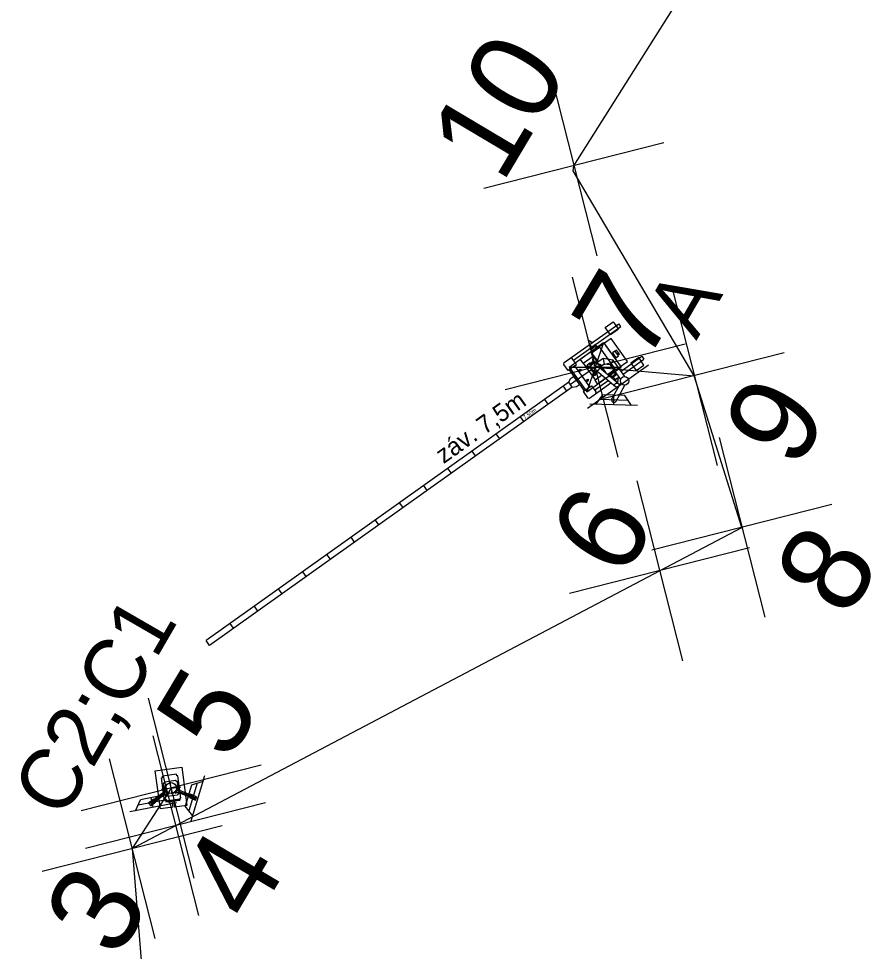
# Model space of a CAD drawing. Extents: x -553584 to -553445, y -1067272 to -1066959.
# Drawn here: x -553576.22 to -553561.85, y -1067237.72 to -1067222.01 of the extents above; entities that cross this region are included whole.
import ezdxf

# ---------------------------------------------------------------- set-up
doc = ezdxf.new("R2010")
doc.units = 0
for name, color, linetype in [('Body', 7, 'Continuous'), ('Default', 7, 'Continuous'), ('Křížky', 7, 'Continuous'), ('Nová kabelizace', 7, 'Continuous'), ('nové prvky ZZ', 7, 'Continuous')]:
    doc.layers.add(name, color=color, linetype=linetype)

# ---------------------------------------------------------------- blocks, each defined once
blk = doc.blocks.new('Křížek')
at = {"layer": 'Křížky'}
for p, q in [((8.84, -8.84), (-8.84, 8.84)), ((8.84, -8.84), (-8.84, 8.84)), ((8.84, -8.84), (-8.84, 8.84)), ((8.84, 8.84), (-8.84, -8.84))]:
    blk.add_line(p, q, dxfattribs=at)

msp = doc.modelspace()

# ---------------------------------------------------------------- linework, layer by layer
at = {"layer": 'Nová kabelizace'}
for p, q in [((-553566.514, -1067227.883), (-553564.846, -1067228.027)), ((-553574.308, -1067235.992), (-553564.043, -1067230.581)), ((-553574.308, -1067235.992), (-553574.04, -1067239.262))]:
    msp.add_line(p, q, dxfattribs=at)
msp.add_lwpolyline([(-553564.043, -1067230.581), (-553564.846, -1067228.027), (-553566.884, -1067224.575), (-553566.87, -1067224.492), (-553564.137, -1067220.156)], dxfattribs=at)
at = {"layer": 'nové prvky ZZ'}
for p, q in [((-553567.034, -1067227.806), (-553566.116, -1067227.152)), ((-553566.081, -1067227.2), (-553566.116, -1067227.152)), ((-553566.879, -1067227.768), (-553566.081, -1067227.2)), ((-553566.951, -1067227.882), (-553566.373, -1067227.47)), ((-553566.373, -1067227.47), (-553566.655, -1067228.297)), ((-553566.605, -1067227.44), (-553566.626, -1067227.455)), ((-553566.626, -1067227.455), (-553566.622, -1067227.461)), ((-553566.622, -1067227.461), (-553566.626, -1067227.463)), ((-553566.626, -1067227.463), (-553566.618, -1067227.473)), ((-553566.605, -1067227.44), (-553566.601, -1067227.446)), ((-553566.601, -1067227.446), (-553566.598, -1067227.443)), ((-553566.598, -1067227.443), (-553566.59, -1067227.453)), ((-553566.374, -1067227.469), (-553566.077, -1067227.884)), ((-553566.569, -1067227.616), (-553566.763, -1067227.754)), ((-553566.595, -1067227.507), (-553566.593, -1067227.492)), ((-553566.592, -1067227.516), (-553566.595, -1067227.507)), ((-553566.569, -1067227.547), (-553566.592, -1067227.516)), ((-553566.569, -1067227.631), (-553566.579, -1067227.646)), ((-553566.579, -1067227.646), (-553566.574, -1067227.663)), ((-553566.445, -1067227.543), (-553566.569, -1067227.631)), ((-553566.511, -1067227.538), (-553566.564, -1067227.576)), ((-553566.438, -1067227.554), (-553566.564, -1067227.644)), ((-553566.564, -1067227.644), (-553566.564, -1067227.658)), ((-553566.339, -1067227.518), (-553566.077, -1067227.884)), ((-553566.179, -1067227.617), (-553566.181, -1067227.614)), ((-553566.899, -1067227.739), (-553566.931, -1067227.733)), ((-553566.826, -1067227.841), (-553566.899, -1067227.739)), ((-553566.763, -1067227.754), (-553566.72, -1067227.814)), ((-553566.713, -1067227.816), (-553566.549, -1067227.699)), ((-553566.545, -1067227.786), (-553566.598, -1067227.824)), ((-553566.534, -1067227.793), (-553566.591, -1067227.833)), ((-553566.574, -1067227.663), (-553566.475, -1067227.803)), ((-553566.564, -1067227.658), (-553566.465, -1067227.796)), ((-553566.558, -1067227.749), (-553566.56, -1067227.759)), ((-553566.56, -1067227.759), (-553566.558, -1067227.768)), ((-553566.553, -1067227.74), (-553566.558, -1067227.749)), ((-553566.558, -1067227.768), (-553566.538, -1067227.796)), ((-553566.531, -1067227.724), (-553566.553, -1067227.74)), ((-553566.524, -1067227.734), (-553566.551, -1067227.753)), ((-553566.551, -1067227.753), (-553566.549, -1067227.762)), ((-553566.549, -1067227.762), (-553566.533, -1067227.784)), ((-553566.38, -1067227.736), (-553566.484, -1067227.81)), ((-553566.209, -1067227.766), (-553566.38, -1067227.736)), ((-553566.38, -1067227.736), (-553566.361, -1067227.83)), ((-553566.209, -1067227.766), (-553566.26, -1067227.846)), ((-553566.012, -1067228.043), (-553566.209, -1067227.766)), ((-553566.077, -1067227.951), (-553565.725, -1067227.7)), ((-553566.043, -1067227.999), (-553565.691, -1067227.748)), ((-553565.725, -1067227.7), (-553565.691, -1067227.748)), ((-553567.039, -1067227.838), (-553567.034, -1067227.806)), ((-553566.966, -1067227.94), (-553567.039, -1067227.838)), ((-553566.952, -1067227.93), (-553566.966, -1067227.94)), ((-553566.951, -1067227.882), (-553566.655, -1067228.297)), ((-553566.951, -1067227.882), (-553566.077, -1067227.884)), ((-553566.514, -1067227.883), (-553566.927, -1067228.178)), ((-553566.855, -1067227.861), (-553566.826, -1067227.841)), ((-553566.72, -1067227.814), (-553566.716, -1067227.811)), ((-553566.716, -1067227.811), (-553566.713, -1067227.816)), ((-553566.713, -1067227.816), (-553566.514, -1067228.095)), ((-553566.655, -1067228.297), (-553566.077, -1067227.884)), ((-553565.615, -1067227.847), (-553566.641, -1067228.578)), ((-553566.569, -1067227.941), (-553566.537, -1067227.969)), ((-553566.541, -1067227.95), (-553566.53, -1067227.96)), ((-553566.501, -1067227.974), (-553566.519, -1067227.96)), ((-553566.518, -1067227.886), (-553566.51, -1067227.88)), ((-553566.511, -1067227.887), (-553566.517, -1067227.879)), ((-553566.483, -1067227.953), (-553566.498, -1067227.964)), ((-553566.474, -1067227.961), (-553566.491, -1067227.973)), ((-553566.169, -1067228.212), (-553566.487, -1067227.95)), ((-553566.469, -1067227.817), (-553566.434, -1067227.845)), ((-553566.453, -1067227.845), (-553566.442, -1067227.854)), ((-553566.425, -1067227.876), (-553566.442, -1067227.887)), ((-553566.127, -1067228.157), (-553566.442, -1067227.896)), ((-553566.424, -1067227.877), (-553566.439, -1067227.865)), ((-553566.424, -1067227.846), (-553566.407, -1067227.859)), ((-553566.407, -1067227.859), (-553566.424, -1067227.877)), ((-553566.423, -1067227.876), (-553566.359, -1067227.964)), ((-553566.361, -1067227.83), (-553566.419, -1067227.871)), ((-553566.414, -1067227.868), (-553566.326, -1067227.992)), ((-553566.26, -1067227.846), (-553566.361, -1067227.83)), ((-553566.196, -1067227.935), (-553566.303, -1067228.011)), ((-553566.26, -1067227.846), (-553566.084, -1067228.092)), ((-553566.779, -1067228.172), (-553566.875, -1067228.037)), ((-553566.534, -1067227.979), (-553566.516, -1067227.993)), ((-553566.522, -1067228.268), (-553566.296, -1067228.107)), ((-553566.516, -1067227.993), (-553566.501, -1067227.974)), ((-553566.515, -1067228.102), (-553566.511, -1067228.1)), ((-553566.472, -1067228.163), (-553566.515, -1067228.102)), ((-553566.514, -1067228.095), (-553566.405, -1067228.018)), ((-553566.511, -1067228.1), (-553566.514, -1067228.095)), ((-553566.472, -1067228.163), (-553566.342, -1067228.07)), ((-553566.22, -1067227.966), (-553566.294, -1067228.019)), ((-553566.293, -1067228.018), (-553566.281, -1067228.02)), ((-553566.237, -1067228.066), (-553566.148, -1067228.002)), ((-553566.213, -1067228.048), (-553566.19, -1067228.08)), ((-553566.19, -1067228.105), (-553566.114, -1067228.05)), ((-553566.19, -1067228.08), (-553566.182, -1067228.085)), ((-553566.182, -1067228.085), (-553566.168, -1067228.089)), ((-553566.151, -1067228.129), (-553566.159, -1067228.119)), ((-553566.123, -1067228.117), (-553566.144, -1067228.132)), ((-553566.123, -1067228.109), (-553566.131, -1067228.099)), ((-553566.127, -1067228.111), (-553566.123, -1067228.109)), ((-553566.123, -1067228.117), (-553566.127, -1067228.111)), ((-553566.956, -1067228.137), (-553573.064, -1067232.489)), ((-553566.898, -1067228.218), (-553573.006, -1067232.57)), ((-553567.052, -1067228.206), (-553566.995, -1067228.287)), ((-553566.898, -1067228.218), (-553566.956, -1067228.137)), ((-553566.609, -1067228.403), (-553566.249, -1067228.146)), ((-553566.603, -1067228.215), (-553566.574, -1067228.195)), ((-553566.574, -1067228.195), (-553566.501, -1067228.297)), ((-553566.232, -1067228.417), (-553566.082, -1067228.146)), ((-553566.162, -1067228.455), (-553566.011, -1067228.186)), ((-553566.148, -1067228.126), (-553566.151, -1067228.129)), ((-553566.144, -1067228.132), (-553566.148, -1067228.126)), ((-553567.305, -1067228.508), (-553567.363, -1067228.427)), ((-553566.699, -1067228.284), (-553566.713, -1067228.294)), ((-553566.713, -1067228.294), (-553566.64, -1067228.397)), ((-553566.64, -1067228.397), (-553566.609, -1067228.403)), ((-553566.501, -1067228.297), (-553566.506, -1067228.329)), ((-553566.501, -1067228.51), (-553566.381, -1067228.35)), ((-553565.956, -1067228.444), (-553566.441, -1067228.43)), ((-553566.011, -1067228.361), (-553566.381, -1067228.35)), ((-553566.193, -1067228.431), (-553566.205, -1067228.443)), ((-553566.205, -1067228.431), (-553566.193, -1067228.443)), ((-553566.201, -1067228.519), (-553566.196, -1067228.355)), ((-553565.901, -1067228.528), (-553566.011, -1067228.361)), ((-553565.801, -1067228.531), (-553566.601, -1067228.507)), ((-553567.712, -1067228.798), (-553567.77, -1067228.717)), ((-553568.12, -1067229.088), (-553568.177, -1067229.008)), ((-553568.527, -1067229.379), (-553568.584, -1067229.298)), ((-553568.934, -1067229.669), (-553568.992, -1067229.588)), ((-553569.341, -1067229.959), (-553569.399, -1067229.878)), ((-553569.748, -1067230.249), (-553569.806, -1067230.168)), ((-553570.156, -1067230.539), (-553570.213, -1067230.458)), ((-553570.563, -1067230.829), (-553570.62, -1067230.748)), ((-553570.97, -1067231.119), (-553571.028, -1067231.039)), ((-553571.377, -1067231.41), (-553571.435, -1067231.329)), ((-553571.784, -1067231.7), (-553571.842, -1067231.619)), ((-553572.192, -1067231.99), (-553572.249, -1067231.909)), ((-553572.599, -1067232.28), (-553572.656, -1067232.199)), ((-553573.006, -1067232.57), (-553573.064, -1067232.489)), ((-553573.919, -1067234.68), (-553573.473, -1067234.62)), ((-553573.833, -1067235.324), (-553573.919, -1067234.68)), ((-553573.473, -1067234.62), (-553573.387, -1067235.264)), ((-553573.816, -1067234.802), (-553573.796, -1067234.8)), ((-553573.765, -1067235.179), (-553573.816, -1067234.802)), ((-553573.562, -1067234.74), (-553573.799, -1067234.771)), ((-553573.796, -1067234.8), (-553573.799, -1067234.771)), ((-553573.78, -1067234.903), (-553573.755, -1067234.87)), ((-553573.576, -1067234.846), (-553573.755, -1067234.87)), ((-553573.653, -1067234.972), (-553573.666, -1067234.872)), ((-553573.542, -1067234.872), (-553573.576, -1067234.846)), ((-553573.558, -1067234.768), (-553573.562, -1067234.74)), ((-553573.538, -1067234.765), (-553573.558, -1067234.768)), ((-553573.518, -1067235.049), (-553573.542, -1067234.872)), ((-553573.487, -1067235.142), (-553573.538, -1067234.765)), ((-553573.091, -1067234.764), (-553573.318, -1067235.532)), ((-553573.12, -1067234.86), (-553573.309, -1067234.924)), ((-553573.653, -1067234.972), (-553574.308, -1067235.992)), ((-553573.653, -1067234.972), (-553573.816, -1067234.994)), ((-553573.756, -1067235.084), (-553573.78, -1067234.903)), ((-553573.771, -1067234.999), (-553573.744, -1067234.978)), ((-553573.706, -1067235.083), (-553573.771, -1067234.999)), ((-553573.768, -1067234.937), (-553573.735, -1067234.932)), ((-553573.754, -1067235.042), (-553573.768, -1067234.937)), ((-553573.653, -1067234.972), (-553573.489, -1067234.95)), ((-553573.653, -1067234.972), (-553573.639, -1067235.073)), ((-553573.53, -1067234.963), (-553573.571, -1067235.061)), ((-553573.565, -1067234.948), (-553573.53, -1067234.963)), ((-553573.516, -1067235.029), (-553573.283, -1067235.125)), ((-553573.508, -1067235.01), (-553573.326, -1067235.085)), ((-553573.309, -1067234.924), (-553573.414, -1067235.279)), ((-553573.214, -1067234.892), (-553573.352, -1067235.357)), ((-553574.249, -1067235.353), (-553574.167, -1067235.171)), ((-553573.732, -1067235.17), (-553574.208, -1067235.262)), ((-553573.804, -1067235.1), (-553574.167, -1067235.171)), ((-553573.944, -1067235.159), (-553573.995, -1067235.273)), ((-553573.954, -1067235.296), (-553573.985, -1067235.136)), ((-553573.77, -1067235.062), (-553573.97, -1067235.216)), ((-553573.782, -1067235.047), (-553573.938, -1067235.167)), ((-553573.757, -1067235.079), (-553573.914, -1067235.199)), ((-553573.66, -1067235.239), (-553573.804, -1067235.1)), ((-553573.765, -1067235.179), (-553573.745, -1067235.176)), ((-553573.756, -1067235.084), (-553573.725, -1067235.109)), ((-553573.717, -1067235.037), (-553573.754, -1067235.042)), ((-553573.745, -1067235.176), (-553573.741, -1067235.205)), ((-553573.743, -1067235.19), (-553573.506, -1067235.159)), ((-553573.741, -1067235.205), (-553573.504, -1067235.173)), ((-553573.725, -1067235.109), (-553573.544, -1067235.085)), ((-553573.676, -1067235.06), (-553573.706, -1067235.083)), ((-553573.571, -1067235.061), (-553573.602, -1067235.048)), ((-553573.518, -1067235.049), (-553573.544, -1067235.085)), ((-553573.524, -1067235.046), (-553573.341, -1067235.122)), ((-553573.487, -1067235.142), (-553573.507, -1067235.144)), ((-553573.507, -1067235.144), (-553573.504, -1067235.173)), ((-553573.205, -1067235.148), (-553573.362, -1067235.102)), ((-553573.345, -1067235.131), (-553573.222, -1067235.119)), ((-553573.244, -1067235.173), (-553573.319, -1067235.082)), ((-553573.561, -1067235.22), (-553574.347, -1067235.372)), ((-553574.031, -1067235.226), (-553573.914, -1067235.207)), ((-553573.625, -1067235.296), (-553573.833, -1067235.324)), ((-553573.608, -1067235.19), (-553573.638, -1067235.194)), ((-553573.638, -1067235.194), (-553573.625, -1067235.296)), ((-553573.608, -1067235.19), (-553573.595, -1067235.292)), ((-553573.387, -1067235.264), (-553573.595, -1067235.292)), ((-553573.29, -1067235.436), (-553573.414, -1067235.279))]:
    msp.add_line(p, q, dxfattribs=at)
for points in [[(-553566.119, -1067227.246), (-553566.253, -1067227.341), (-553566.342, -1067227.215), (-553566.209, -1067227.12)], [(-553566.246, -1067227.4), (-553566.445, -1067227.543), (-553566.169, -1067227.93), (-553565.97, -1067227.788)], [(-553566.509, -1067227.504), (-553566.597, -1067227.567), (-553566.589, -1067227.579), (-553566.501, -1067227.516)], [(-553566.464, -1067227.534), (-553566.505, -1067227.564), (-553566.495, -1067227.578), (-553566.453, -1067227.548)], [(-553566.529, -1067227.785), (-553566.522, -1067227.78), (-553566.511, -1067227.795), (-553566.518, -1067227.8)], [(-553565.78, -1067227.721), (-553565.914, -1067227.816), (-553565.824, -1067227.942), (-553565.691, -1067227.847)], [(-553566.855, -1067227.861), (-553566.952, -1067227.93), (-553566.699, -1067228.284), (-553566.603, -1067228.215)], [(-553566.644, -1067227.857), (-553566.657, -1067227.867), (-553566.644, -1067227.886), (-553566.631, -1067227.876)], [(-553566.544, -1067227.997), (-553566.557, -1067228.007), (-553566.544, -1067228.026), (-553566.531, -1067228.016)], [(-553573.722, -1067235.061), (-553573.757, -1067235.016), (-553573.787, -1067235.04), (-553573.753, -1067235.085)], [(-553573.541, -1067234.988), (-553573.562, -1067235.04), (-553573.527, -1067235.055), (-553573.505, -1067235.003)], [(-553573.908, -1067235.206), (-553573.944, -1067235.159), (-553574.031, -1067235.226), (-553573.995, -1067235.273)], [(-553573.323, -1067235.077), (-553573.345, -1067235.131), (-553573.244, -1067235.173), (-553573.222, -1067235.119)]]:
    msp.add_lwpolyline(points, close=True, dxfattribs=at)
for points in [[(-553566.618, -1067227.473), (-553566.622, -1067227.476), (-553566.611, -1067227.492)], [(-553566.611, -1067227.492), (-553566.62, -1067227.499), (-553566.614, -1067227.507), (-553566.56, -1067227.468), (-553566.566, -1067227.46), (-553566.575, -1067227.467)], [(-553566.575, -1067227.467), (-553566.587, -1067227.451), (-553566.59, -1067227.453)], [(-553566.564, -1067227.576), (-553566.586, -1067227.592), (-553566.566, -1067227.62), (-553566.5, -1067227.573)], [(-553566.511, -1067227.538), (-553566.518, -1067227.528), (-553566.571, -1067227.566), (-553566.564, -1067227.576)], [(-553566.475, -1067227.542), (-553566.489, -1067227.523), (-553566.511, -1067227.538)], [(-553566.181, -1067227.614), (-553566.222, -1067227.644), (-553566.164, -1067227.725), (-553566.118, -1067227.692), (-553566.143, -1067227.657)], [(-553566.122, -1067227.642), (-553566.153, -1067227.598), (-553566.179, -1067227.617), (-553566.148, -1067227.661), (-553566.132, -1067227.649)], [(-553566.132, -1067227.649), (-553566.115, -1067227.673), (-553566.105, -1067227.666), (-553566.122, -1067227.642)], [(-553566.519, -1067227.804), (-553566.516, -1067227.802), (-553566.532, -1067227.78), (-553566.539, -1067227.786), (-553566.526, -1067227.805)], [(-553566.754, -1067227.937), (-553566.751, -1067227.941), (-553566.782, -1067227.964), (-553566.799, -1067227.94), (-553566.768, -1067227.918), (-553566.765, -1067227.922)], [(-553566.765, -1067227.922), (-553566.758, -1067227.917), (-553566.747, -1067227.932), (-553566.754, -1067227.937)], [(-553566.588, -1067227.854), (-553566.61, -1067227.822), (-553566.649, -1067227.85), (-553566.626, -1067227.883), (-553566.589, -1067227.857)], [(-553566.583, -1067227.844), (-553566.608, -1067227.81), (-553566.615, -1067227.815), (-553566.588, -1067227.854), (-553566.588, -1067227.854)], [(-553566.526, -1067227.955), (-553566.547, -1067227.98), (-553566.54, -1067227.986), (-553566.515, -1067227.956)], [(-553566.515, -1067227.956), (-553566.504, -1067227.972)], [(-553566.502, -1067227.975), (-553566.482, -1067228.004), (-553566.474, -1067227.998), (-553566.504, -1067227.955)], [(-553566.446, -1067227.859), (-553566.425, -1067227.833), (-553566.418, -1067227.839), (-553566.443, -1067227.869)], [(-553566.18, -1067227.958), (-553566.21, -1067227.98), (-553566.22, -1067227.966), (-553566.19, -1067227.944)], [(-553566.956, -1067228.137), (-553566.926, -1067228.075), (-553566.875, -1067228.038)], [(-553566.632, -1067228.108), (-553566.629, -1067228.113), (-553566.66, -1067228.135), (-553566.677, -1067228.111), (-553566.646, -1067228.089), (-553566.643, -1067228.093)], [(-553566.643, -1067228.093), (-553566.636, -1067228.088), (-553566.625, -1067228.104), (-553566.632, -1067228.108)], [(-553566.541, -1067227.984), (-553566.549, -1067227.99), (-553566.526, -1067228.023), (-553566.487, -1067227.996)], [(-553566.265, -1067228.043), (-553566.281, -1067228.02), (-553566.215, -1067227.973)], [(-553566.24, -1067228.031), (-553566.261, -1067228.046)], [(-553566.246, -1067228.058), (-553566.159, -1067227.996), (-553566.152, -1067228.005), (-553566.237, -1067228.066)], [(-553566.187, -1067227.993), (-553566.176, -1067228.008), (-553566.229, -1067228.046), (-553566.24, -1067228.031)], [(-553566.186, -1067228.108), (-553566.189, -1067228.104), (-553566.135, -1067228.065), (-553566.129, -1067228.073), (-553566.139, -1067228.08)], [(-553566.166, -1067227.978), (-553566.187, -1067227.993)], [(-553566.174, -1067228.105), (-553566.182, -1067228.111)], [(-553566.159, -1067228.119), (-553566.162, -1067228.121), (-553566.174, -1067228.105)], [(-553566.139, -1067228.08), (-553566.127, -1067228.096), (-553566.131, -1067228.099)], [(-553566.898, -1067228.218), (-553566.829, -1067228.21), (-553566.778, -1067228.174)], [(-553573.743, -1067235.19), (-553573.741, -1067235.205), (-553573.504, -1067235.173), (-553573.506, -1067235.159), (-553573.743, -1067235.19)]]:
    msp.add_lwpolyline(points, dxfattribs=at)
for centre, radius in [((-553566.514, -1067227.883), 0.0725), ((-553566.017, -1067228.114), 0.0716), ((-553566.148, -1067228.185), 0.0347), ((-553566.199, -1067228.437), 0.00856), ((-553573.653, -1067234.972), 0.0915)]:
    msp.add_circle(centre, radius, dxfattribs=at)
for centre, radius, start, end in [((-553566.514, -1067227.883), 0.0795, 55.9192, 226.4532), ((-553566.196, -1067228.436), 0.0399, 149.4481, 331.155)]:
    msp.add_arc(centre, radius, start, end, dxfattribs=at)

# ---------------------------------------------------------------- block references
at = {"layer": 'Body', "xscale": 0.12500000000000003, "yscale": 0.125, "rotation": 59.23917986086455}
for p in [(-553566.87, -1067224.492), (-553566.514, -1067227.883), (-553564.846, -1067228.027), (-553564.043, -1067230.581), (-553565.429, -1067231.312), (-553573.653, -1067234.972), (-553573.576, -1067235.606), (-553574.308, -1067235.992)]:
    msp.add_blockref('Křížek', p, dxfattribs=at)

# ---------------------------------------------------------------- texts
at = {"layer": 'Default'}
for s, p in [('10', (-553568.082, -1067224.814)), ('7', (-553565.679, -1067227.857)), ('9', (-553563.135, -1067229.639)), ('6', (-553566.053, -1067231.485)), ('8', (-553562.267, -1067232.141)), ('5', (-553572.687, -1067234.554)), ('4', (-553572.272, -1067237.288)), ('3', (-553574.565, -1067237.877))]:
    msp.add_text(s, height=1.5, rotation=59.2392, dxfattribs=at).set_placement(p)
at = {"layer": 'nové prvky ZZ'}
for s, height, rotation, p in [('A', 1.025, 59.9447, (-553564.81, -1067227.444)), ('265', 0.025, 35.4719, (-553566.55, -1067227.869)), ('záv. 7,5m', 0.3, 35.4719, (-553569.064, -1067229.518)), ('7,50m', 0.0646, 35.4719, (-553567.698, -1067228.763)), ('C2;C1', 1.0248, 59.9447, (-553575.475, -1067235.522))]:
    msp.add_text(s, height=height, rotation=rotation, dxfattribs=at).set_placement(p)

doc.saveas('drawing.dxf')
